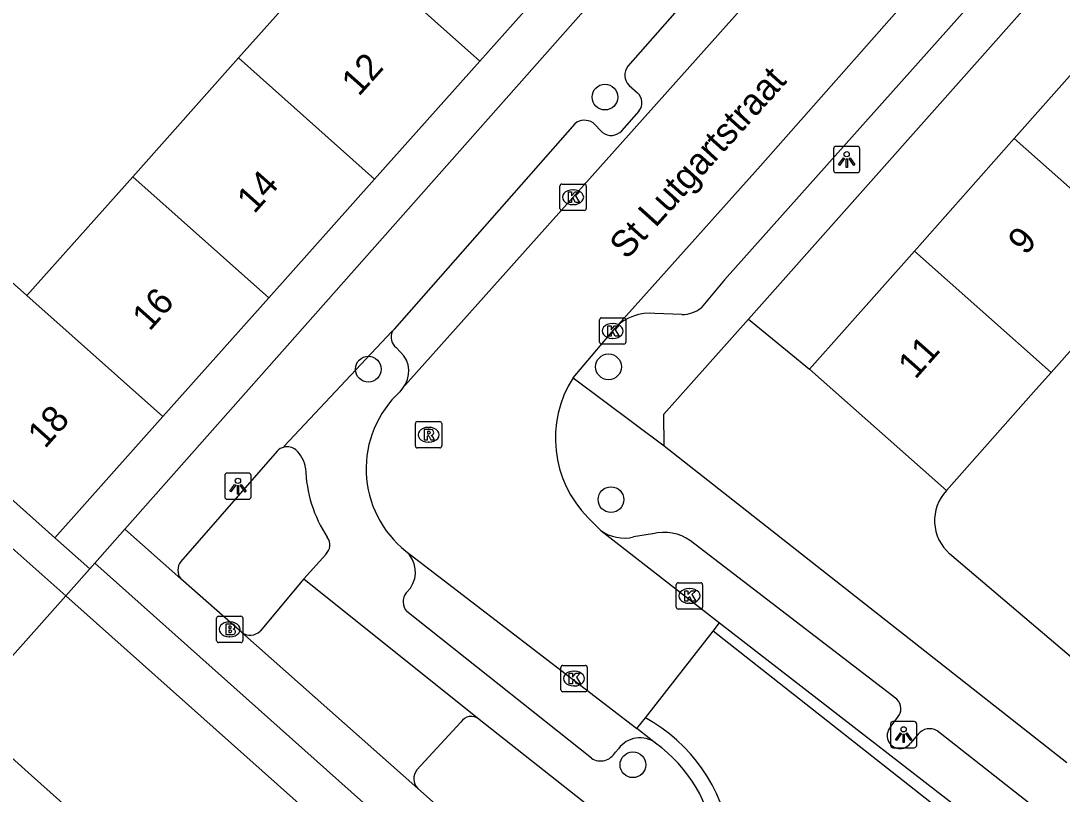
# Model space of a CAD drawing. Extents: x 162812 to 163818, y 381639 to 382470.
# Drawn here: x 162894.41 to 162934, y 382010.31 to 382039.7 of the extents above; entities that cross this region are included whole.
import ezdxf

# ---------------------------------------------------------------- set-up
doc = ezdxf.new("R2010")
doc.units = 0
for name, color, linetype in [('IMGEO_Boom', 7, 'Continuous'), ('IMGEO_Brandkraan', 7, 'Continuous'), ('IMGEO_Groenvoorziening', 7, 'Continuous'), ('IMGEO_Kolk', 7, 'Continuous'), ('IMGEO_Lichtpunt', 7, 'Continuous'), ('IMGEO_Openbare_ruimte_label', 7, 'Continuous'), ('IMGEO_Pand', 7, 'Continuous'), ('IMGEO_Pand_nummerreeks', 7, 'Continuous'), ('IMGEO_Pand_overbouw', 7, 'Continuous'), ('IMGEO_Rijbaan_lokaal_open', 7, 'Continuous'), ('IMGEO_Rioolput', 7, 'Continuous'), ('IMGEO_Voetpad_open', 7, 'Continuous')]:
    doc.layers.add(name, color=color, linetype=linetype)

msp = doc.modelspace()

# ---------------------------------------------------------------- linework, layer by layer
at = {"layer": 'IMGEO_Boom'}
for centre in [(162916.617, 382036.802), (162907.619, 382026.464), (162916.751, 382026.553), (162916.846, 382021.506), (162917.679, 382011.429)]:
    msp.add_circle(centre, 0.489, dxfattribs=at)
at = {"layer": 'IMGEO_Brandkraan'}
for p, q in [((162901.85, 382016.15), (162901.85, 382017.002)), ((162901.925, 382017.076), (162902.777, 382017.076)), ((162902.338, 382016.856), (162902.363, 382016.856)), ((162902.851, 382017.002), (162902.851, 382016.15)), ((162902.777, 382016.076), (162901.925, 382016.076)), ((162902.361, 382016.296), (162902.336, 382016.296))]:
    msp.add_line(p, q, dxfattribs=at)
for points in [[(162901.85, 382016.15), (162901.85, 382017.002)], [(162901.925, 382017.076), (162902.777, 382017.076)], [(162902.851, 382017.002), (162902.851, 382016.15)], [(162902.198, 382016.776), (162902.198, 382016.376), (162902.411, 382016.376)], [(162902.429, 382016.776), (162902.198, 382016.776)], [(162902.377, 382016.695), (162902.323, 382016.695), (162902.323, 382016.619)], [(162902.323, 382016.619), (162902.376, 382016.619)], [(162902.385, 382016.543), (162902.323, 382016.543), (162902.323, 382016.462)], [(162902.323, 382016.462), (162902.385, 382016.462)], [(162902.777, 382016.076), (162901.925, 382016.076)]]:
    msp.add_lwpolyline(points, dxfattribs=at)
for centre, radius, start, end in [((162901.927, 382017), 0.0765, 91.552, 178.448), ((162901.927, 382017), 0.0765, 91.552, 178.448), ((162902.775, 382017), 0.0765, 1.552, 88.448), ((162902.775, 382017), 0.0765, 1.552, 88.448), ((162902.378, 382016.657), 0.0379, 267.8285, 90.9355), ((162902.386, 382016.502), 0.0404, 269.8759, 90.5077), ((162902.433, 382016.631), 0.145, 59.4692, 91.5367), ((162902.458, 382016.678), 0.0922, 285.5137, 58.1501), ((162902.463, 382016.486), 0.105, 301.3115, 78.989), ((162901.927, 382016.152), 0.0765, 181.552, 268.448), ((162901.927, 382016.152), 0.0765, 181.552, 268.448), ((162902.417, 382016.627), 0.251, 268.6676, 293.5347), ((162902.775, 382016.152), 0.0765, 271.552, 358.448), ((162902.775, 382016.152), 0.0765, 271.552, 358.448)]:
    msp.add_arc(centre, radius, start, end, dxfattribs=at)
for centre, major_axis, ratio, start_param, end_param in [((162902.337, 382016.576), (-0.387, 0.002), 0.722429, 4.712389, 7.853982), ((162902.362, 382016.576), (-0.39, 0.002), 0.717154, 1.570796, 4.712389)]:
    msp.add_ellipse(centre, major_axis=major_axis, ratio=ratio, start_param=start_param, end_param=end_param, dxfattribs=at)
at = {"layer": 'IMGEO_Groenvoorziening'}
for points in [[(162922.075, 382028.37), (162924.398, 382026.461)], [(162936.109, 382014.006), (162929.716, 382019.448)]]:
    msp.add_lwpolyline(points, dxfattribs=at)
msp.add_arc((162930.828, 382020.708), 1.68, 137.2155, 228.5546, dxfattribs=at)
at = {"layer": 'IMGEO_Kolk'}
for p, q in [((162914.98, 382033.497), (162915.832, 382033.497)), ((162914.905, 382032.571), (162914.905, 382033.423)), ((162915.393, 382033.277), (162915.418, 382033.277)), ((162915.906, 382033.423), (162915.906, 382032.571)), ((162915.416, 382032.717), (162915.391, 382032.717)), ((162915.832, 382032.497), (162914.98, 382032.497)), ((162916.41, 382027.489), (162916.41, 382028.341)), ((162916.485, 382028.415), (162917.337, 382028.415)), ((162917.411, 382028.341), (162917.411, 382027.489)), ((162916.898, 382028.195), (162916.923, 382028.195)), ((162916.921, 382027.635), (162916.896, 382027.635)), ((162917.337, 382027.415), (162916.485, 382027.415)), ((162919.329, 382017.42), (162919.329, 382018.272)), ((162919.404, 382018.346), (162920.256, 382018.346)), ((162919.817, 382018.126), (162919.842, 382018.126)), ((162920.33, 382018.272), (162920.33, 382017.42)), ((162920.256, 382017.346), (162919.404, 382017.346)), ((162919.84, 382017.566), (162919.815, 382017.566)), ((162914.939, 382014.28), (162914.939, 382015.132)), ((162915.014, 382015.206), (162915.866, 382015.206)), ((162915.427, 382014.986), (162915.452, 382014.986)), ((162915.94, 382015.132), (162915.94, 382014.28)), ((162915.866, 382014.206), (162915.014, 382014.206)), ((162915.45, 382014.426), (162915.425, 382014.426))]:
    msp.add_line(p, q, dxfattribs=at)
for points in [[(162914.98, 382033.497), (162915.832, 382033.497)], [(162914.905, 382032.571), (162914.905, 382033.423)], [(162915.226, 382033.197), (162915.349, 382033.197), (162915.349, 382033.046), (162915.479, 382033.197), (162915.643, 382033.197), (162915.497, 382033.046), (162915.65, 382032.797), (162915.498, 382032.797), (162915.413, 382032.961), (162915.349, 382032.894), (162915.349, 382032.797), (162915.226, 382032.797), (162915.226, 382033.197)], [(162915.906, 382033.423), (162915.906, 382032.571)], [(162915.832, 382032.497), (162914.98, 382032.497)], [(162916.41, 382027.489), (162916.41, 382028.341)], [(162916.485, 382028.415), (162917.337, 382028.415)], [(162917.411, 382028.341), (162917.411, 382027.489)], [(162916.731, 382028.115), (162916.854, 382028.115), (162916.854, 382027.964), (162916.984, 382028.115), (162917.148, 382028.115), (162917.002, 382027.964), (162917.155, 382027.715), (162917.003, 382027.715), (162916.918, 382027.879), (162916.854, 382027.812), (162916.854, 382027.715), (162916.731, 382027.715), (162916.731, 382028.115)], [(162917.337, 382027.415), (162916.485, 382027.415)], [(162919.329, 382017.42), (162919.329, 382018.272)], [(162919.404, 382018.346), (162920.256, 382018.346)], [(162919.65, 382018.046), (162919.773, 382018.046), (162919.773, 382017.895), (162919.903, 382018.046), (162920.067, 382018.046), (162919.921, 382017.895), (162920.074, 382017.646), (162919.922, 382017.646), (162919.837, 382017.81), (162919.773, 382017.743), (162919.773, 382017.646), (162919.65, 382017.646), (162919.65, 382018.046)], [(162920.33, 382018.272), (162920.33, 382017.42)], [(162920.256, 382017.346), (162919.404, 382017.346)], [(162914.939, 382014.28), (162914.939, 382015.132)], [(162915.014, 382015.206), (162915.866, 382015.206)], [(162915.26, 382014.906), (162915.383, 382014.906), (162915.383, 382014.755), (162915.513, 382014.906), (162915.677, 382014.906), (162915.531, 382014.755), (162915.684, 382014.506), (162915.532, 382014.506), (162915.447, 382014.67), (162915.383, 382014.603), (162915.383, 382014.506), (162915.26, 382014.506), (162915.26, 382014.906)], [(162915.94, 382015.132), (162915.94, 382014.28)], [(162915.866, 382014.206), (162915.014, 382014.206)]]:
    msp.add_lwpolyline(points, dxfattribs=at)
for centre, start, end in [((162914.982, 382033.421), 91.552, 178.448), ((162914.982, 382033.421), 91.552, 178.448), ((162915.83, 382033.421), 1.552, 88.448), ((162915.83, 382033.421), 1.552, 88.448), ((162914.982, 382032.573), 181.552, 268.448), ((162914.982, 382032.573), 181.552, 268.448), ((162915.83, 382032.573), 271.552, 358.448), ((162915.83, 382032.573), 271.552, 358.448), ((162916.487, 382028.339), 91.552, 178.448), ((162916.487, 382028.339), 91.552, 178.448), ((162917.335, 382028.339), 1.552, 88.448), ((162917.335, 382028.339), 1.552, 88.448), ((162916.487, 382027.491), 181.552, 268.448), ((162916.487, 382027.491), 181.552, 268.448), ((162917.335, 382027.491), 271.552, 358.448), ((162917.335, 382027.491), 271.552, 358.448), ((162919.406, 382018.27), 91.552, 178.448), ((162919.406, 382018.27), 91.552, 178.448), ((162920.254, 382018.27), 1.552, 88.448), ((162920.254, 382018.27), 1.552, 88.448), ((162919.406, 382017.422), 181.552, 268.448), ((162919.406, 382017.422), 181.552, 268.448), ((162920.254, 382017.422), 271.552, 358.448), ((162920.254, 382017.422), 271.552, 358.448), ((162915.016, 382015.13), 91.552, 178.448), ((162915.016, 382015.13), 91.552, 178.448), ((162915.864, 382015.13), 1.552, 88.448), ((162915.864, 382015.13), 1.552, 88.448), ((162915.016, 382014.282), 181.552, 268.448), ((162915.016, 382014.282), 181.552, 268.448), ((162915.864, 382014.282), 271.552, 358.448), ((162915.864, 382014.282), 271.552, 358.448)]:
    msp.add_arc(centre, 0.0765, start, end, dxfattribs=at)
for centre, major_axis, ratio, start_param, end_param in [((162915.392, 382032.997), (-0.387, 0.002), 0.722429, 4.712389, 7.853982), ((162915.417, 382032.997), (-0.39, 0.002), 0.717154, 1.570796, 4.712389), ((162916.897, 382027.915), (-0.387, 0.002), 0.722429, 4.712389, 7.853982), ((162916.922, 382027.915), (-0.39, 0.002), 0.717154, 1.570796, 4.712389), ((162919.816, 382017.846), (-0.387, 0.002), 0.722429, 4.712389, 7.853982), ((162919.841, 382017.846), (-0.39, 0.002), 0.717154, 1.570796, 4.712389), ((162915.426, 382014.706), (-0.387, 0.002), 0.722429, 4.712389, 7.853982), ((162915.451, 382014.706), (-0.39, 0.002), 0.717154, 1.570796, 4.712389)]:
    msp.add_ellipse(centre, major_axis=major_axis, ratio=ratio, start_param=start_param, end_param=end_param, dxfattribs=at)
at = {"layer": 'IMGEO_Lichtpunt'}
for p, q in [((162925.308, 382034.835), (162925.308, 382034.028)), ((162925.308, 382034.835), (162925.308, 382034.028)), ((162926.21, 382034.93), (162925.402, 382034.93)), ((162926.21, 382034.93), (162925.402, 382034.93)), ((162926.304, 382034.028), (162926.304, 382034.835)), ((162926.304, 382034.028), (162926.304, 382034.835)), ((162925.402, 382033.934), (162926.21, 382033.934)), ((162925.402, 382033.934), (162926.21, 382033.934)), ((162902.165, 382022.422), (162902.165, 382021.615)), ((162902.165, 382022.422), (162902.165, 382021.615)), ((162903.067, 382022.517), (162902.259, 382022.517)), ((162903.067, 382022.517), (162902.259, 382022.517)), ((162903.161, 382021.615), (162903.161, 382022.422)), ((162903.161, 382021.615), (162903.161, 382022.422)), ((162902.259, 382021.521), (162903.067, 382021.521)), ((162902.259, 382021.521), (162903.067, 382021.521)), ((162927.472, 382012.98), (162927.472, 382012.173)), ((162927.472, 382012.98), (162927.472, 382012.173)), ((162928.374, 382013.075), (162927.566, 382013.075)), ((162928.374, 382013.075), (162927.566, 382013.075)), ((162928.468, 382012.173), (162928.468, 382012.98)), ((162928.468, 382012.173), (162928.468, 382012.98)), ((162927.566, 382012.079), (162928.374, 382012.079)), ((162927.566, 382012.079), (162928.374, 382012.079))]:
    msp.add_line(p, q, dxfattribs=at)
for points in [[(162925.682, 382034.499), (162925.721, 382034.471), (162925.533, 382034.209), (162925.495, 382034.236), (162925.682, 382034.499)], [(162925.784, 382034.451), (162925.831, 382034.451), (162925.831, 382034.129), (162925.784, 382034.129), (162925.784, 382034.451)], [(162925.894, 382034.471), (162925.932, 382034.498), (162926.119, 382034.236), (162926.08, 382034.208), (162925.894, 382034.471)], [(162902.539, 382022.086), (162902.578, 382022.058), (162902.39, 382021.796), (162902.352, 382021.823), (162902.539, 382022.086)], [(162902.641, 382022.038), (162902.688, 382022.038), (162902.688, 382021.716), (162902.641, 382021.716), (162902.641, 382022.038)], [(162902.751, 382022.058), (162902.789, 382022.085), (162902.976, 382021.823), (162902.937, 382021.795), (162902.751, 382022.058)], [(162927.846, 382012.644), (162927.885, 382012.616), (162927.697, 382012.354), (162927.659, 382012.381), (162927.846, 382012.644)], [(162927.948, 382012.596), (162927.995, 382012.596), (162927.995, 382012.274), (162927.948, 382012.274), (162927.948, 382012.596)], [(162928.058, 382012.616), (162928.096, 382012.643), (162928.283, 382012.381), (162928.244, 382012.353), (162928.058, 382012.616)]]:
    msp.add_lwpolyline(points, dxfattribs=at)
for centre in [(162925.807, 382034.633), (162902.664, 382022.22), (162927.971, 382012.778)]:
    msp.add_circle(centre, 0.0994, dxfattribs=at)
for centre, start, end in [((162925.402, 382034.835), 90, 180), ((162925.402, 382034.835), 90, 180), ((162926.21, 382034.835), 0, 90), ((162926.21, 382034.835), 0, 90), ((162925.402, 382034.028), 180, 270), ((162925.402, 382034.028), 180, 270), ((162926.21, 382034.028), 270, 0), ((162926.21, 382034.028), 270, 360), ((162902.259, 382022.422), 90, 180), ((162902.259, 382022.422), 90, 180), ((162903.067, 382022.422), 0, 90), ((162903.067, 382022.422), 0, 90), ((162902.259, 382021.615), 180, 270), ((162902.259, 382021.615), 180, 270), ((162903.067, 382021.615), 270, 0), ((162903.067, 382021.615), 270, 360), ((162927.566, 382012.98), 90, 180), ((162927.566, 382012.98), 90, 180), ((162928.374, 382012.98), 0, 90), ((162928.374, 382012.98), 0, 90), ((162927.566, 382012.173), 180, 270), ((162927.566, 382012.173), 180, 270), ((162928.374, 382012.173), 270, 0), ((162928.374, 382012.173), 270, 360)]:
    msp.add_arc(centre, 0.0946, start, end, dxfattribs=at)
at = {"layer": 'IMGEO_Pand'}
for points in [[(162906.69, 382042.781), (162902.686, 382038.29)], [(162906.69, 382042.781), (162911.858, 382038.173)], [(162911.858, 382038.173), (162915.664, 382042.443)], [(162932.179, 382035.23), (162935.991, 382039.525)], [(162902.686, 382038.29), (162898.664, 382033.778)], [(162907.855, 382033.683), (162902.686, 382038.29)], [(162907.855, 382033.683), (162911.858, 382038.173)], [(162928.379, 382030.947), (162932.179, 382035.23)], [(162937.377, 382030.619), (162932.179, 382035.23)], [(162898.664, 382033.778), (162894.644, 382029.268)], [(162898.664, 382033.778), (162903.833, 382029.17)], [(162903.833, 382029.17), (162907.855, 382033.683)], [(162888.693, 382026.299), (162892.789, 382030.894), (162894.644, 382029.268)], [(162924.398, 382026.461), (162928.379, 382030.947)], [(162933.576, 382026.335), (162928.379, 382030.947)], [(162933.576, 382026.335), (162937.377, 382030.619)], [(162894.644, 382029.268), (162899.812, 382024.661)], [(162899.812, 382024.661), (162903.833, 382029.17)], [(162924.398, 382026.461), (162929.595, 382021.849)], [(162929.595, 382021.849), (162932.914, 382025.589), (162933.576, 382026.335)], [(162895.703, 382020.051), (162891.971, 382023.378), (162890.534, 382024.658), (162888.693, 382026.299)], [(162899.812, 382024.661), (162895.703, 382020.051)], [(162893.84, 382019.876), (162896.127, 382017.855)], [(162896.127, 382017.855), (162892.152, 382013.4)], [(162910.955, 382006.836), (162909.879, 382005.585), (162896.127, 382017.855)], [(162892.152, 382013.4), (162894.821, 382011.019), (162907.817, 381999.423)]]:
    msp.add_lwpolyline(points, dxfattribs=at)
at = {"layer": 'IMGEO_Pand_overbouw'}
msp.add_lwpolyline([(162896.127, 382017.855), (162909.879, 382005.585), (162910.955, 382006.836), (162897.226, 382019.086)], close=True, dxfattribs=at)
at = {"layer": 'IMGEO_Rijbaan_lokaal_open'}
for points in [[(162940.419, 382061.006), (162908.926, 382025.738)], [(162917.005, 382028.023), (162922.534, 382034.193), (162929.723, 382042.344), (162932.733, 382045.731), (162937.653, 382051.145), (162938.019, 382051.566)], [(162915.402, 382026.137), (162917.005, 382028.023)], [(162908.926, 382025.738), (162908.824, 382025.608)], [(162916.457, 382020.33), (162915.978, 382020.815)], [(162916.457, 382020.33), (162920.977, 382016.827)], [(162909.048, 382019.549), (162917.831, 382012.803)], [(162920.73, 382016.511), (162920.977, 382016.827)], [(162920.977, 382016.827), (162934.305, 382006.499)], [(162918.155, 382013.213), (162920.73, 382016.511)], [(162933.979, 382006.075), (162920.73, 382016.511)], [(162917.831, 382012.803), (162918.155, 382013.213)], [(162918.543, 382012.256), (162917.831, 382012.803)]]:
    msp.add_lwpolyline(points, dxfattribs=at)
for centre, radius, start, end in [((162919.015, 382023.836), 4.284, 147.5103, 224.8439), ((162911.525, 382022.674), 3.988, 132.6367, 231.5978), ((162915.144, 382007.68), 6.3, 315.0863, 61.4454), ((162915.122, 382007.604), 5.774, 323.9457, 53.6653)]:
    msp.add_arc(centre, radius, start, end, dxfattribs=at)
at = {"layer": 'IMGEO_Rioolput'}
for p, q in [((162909.41, 382023.546), (162909.41, 382024.398)), ((162909.485, 382024.472), (162910.337, 382024.472)), ((162910.411, 382024.398), (162910.411, 382023.546)), ((162909.898, 382024.252), (162909.923, 382024.252)), ((162909.921, 382023.692), (162909.896, 382023.692)), ((162910.337, 382023.472), (162909.485, 382023.472))]:
    msp.add_line(p, q, dxfattribs=at)
for points in [[(162909.41, 382023.546), (162909.41, 382024.398)], [(162909.485, 382024.472), (162910.337, 382024.472)], [(162910.411, 382024.398), (162910.411, 382023.546)], [(162909.999, 382024.17), (162909.747, 382024.172), (162909.747, 382023.772)], [(162909.747, 382023.772), (162909.871, 382023.772), (162909.871, 382023.934), (162909.882, 382023.934)], [(162909.925, 382024.091), (162909.871, 382024.091), (162909.871, 382024.01)], [(162909.871, 382024.01), (162909.923, 382024.01)], [(162909.929, 382023.905), (162910, 382023.772), (162910.14, 382023.772), (162910.075, 382023.898)], [(162910.337, 382023.472), (162909.485, 382023.472)]]:
    msp.add_lwpolyline(points, dxfattribs=at)
for centre, radius, start, end in [((162909.487, 382024.396), 0.0765, 91.552, 178.448), ((162909.487, 382024.396), 0.0765, 91.552, 178.448), ((162910.335, 382024.396), 0.0765, 1.552, 88.448), ((162910.335, 382024.396), 0.0765, 1.552, 88.448), ((162909.881, 382023.881), 0.0533, 26.0293, 88.6989), ((162909.907, 382024.199), 0.19, 274.7715, 282.9687), ((162909.931, 382023.995), 0.0964, 77.0061, 93.1865), ((162909.945, 382024.052), 0.0378, 276.6634, 79.6772), ((162909.998, 382024.06), 0.109, 350.3612, 89.416), ((162909.996, 382024.06), 0.112, 277.5842, 350.9817), ((162909.98, 382023.845), 0.108, 29.5134, 73.7905), ((162909.487, 382023.548), 0.0765, 181.552, 268.448), ((162909.487, 382023.548), 0.0765, 181.552, 268.448), ((162910.335, 382023.548), 0.0765, 271.552, 358.448), ((162910.335, 382023.548), 0.0765, 271.552, 358.448)]:
    msp.add_arc(centre, radius, start, end, dxfattribs=at)
for centre, major_axis, ratio, start_param, end_param in [((162909.897, 382023.972), (-0.387, 0.002), 0.722429, 4.712389, 7.853982), ((162909.922, 382023.972), (-0.39, 0.002), 0.717154, 1.570796, 4.712389)]:
    msp.add_ellipse(centre, major_axis=major_axis, ratio=ratio, start_param=start_param, end_param=end_param, dxfattribs=at)
at = {"layer": 'IMGEO_Voetpad_open'}
for points in [[(162939.702, 382067.058), (162898.37, 382020.378)], [(162922.075, 382028.37), (162948.951, 382058.608)], [(162921.15, 382042.148), (162917.488, 382037.977)], [(162929.979, 382041.25), (162930.725, 382040.584), (162921.155, 382029.858), (162920.269, 382028.791)], [(162917.531, 382037.248), (162917.848, 382036.965)], [(162917.903, 382036.269), (162917.251, 382035.524)], [(162916.525, 382035.457), (162916.165, 382035.823)], [(162915.469, 382035.792), (162908.602, 382027.984)], [(162919.54, 382028.543), (162918.518, 382028.583)], [(162918.865, 382023.545), (162918.856, 382024.749), (162922.075, 382028.37)], [(162908.54, 382027.894), (162908.519, 382027.895), (162904.421, 382023.535), (162904.417, 382023.5)], [(162908.842, 382027.115), (162908.678, 382027.282)], [(162915.402, 382026.137), (162918.865, 382023.545)], [(162918.865, 382023.545), (162934.177, 382011.519)], [(162904.153, 382023.353), (162900.491, 382019.159)], [(162898.37, 382020.378), (162897.226, 382019.086)], [(162900.498, 382018.497), (162898.37, 382020.378)], [(162895.703, 382020.051), (162897.033, 382018.87)], [(162918.43, 382020.202), (162917.707, 382020.086)], [(162927.707, 382013.918), (162919.865, 382019.942)], [(162905.999, 382019.424), (162905.174, 382018.492)], [(162896.127, 382017.855), (162897.033, 382018.87)], [(162897.033, 382018.87), (162897.226, 382019.086)], [(162897.226, 382019.086), (162910.955, 382006.836)], [(162902.815, 382016.451), (162900.498, 382018.497)], [(162905.174, 382018.492), (162903.507, 382016.508)], [(162905.174, 382018.492), (162911.835, 382013.162)], [(162909.063, 382017.966), (162909.218, 382018.147)], [(162916.099, 382011.678), (162909.084, 382017.252)], [(162902.815, 382016.451), (162909.498, 382010.533)], [(162911.133, 382013.051), (162909.468, 382011.233)], [(162911.835, 382013.162), (162918.224, 382008.118)], [(162927.456, 382012.849), (162927.733, 382013.225)], [(162928.525, 382012.597), (162928.234, 382012.253)], [(162939.983, 382004.281), (162929.241, 382012.721)], [(162917.137, 382012.041), (162917.014, 382011.915)], [(162909.498, 382010.533), (162915.518, 382005.2)]]:
    msp.add_lwpolyline(points, dxfattribs=at)
for centre, radius, start, end in [((162917.932, 382037.637), 0.559, 142.5992, 224.1522), ((162917.539, 382036.59), 0.486, 318.5713, 50.4652), ((162915.838, 382035.331), 0.591, 56.4236, 128.677), ((162916.852, 382035.885), 0.539, 232.6818, 317.8636), ((162919.551, 382029.705), 1.162, 269.4431, 308.1327), ((162918.317, 382026.803), 1.791, 83.5486, 137.073), ((162908.967, 382027.669), 0.482, 152.15, 233.2642), ((162909.012, 382027.635), 0.538, 139.6088, 151.2661), ((162908.16, 382026.382), 1.001, 319.9478, 47.0339), ((162904.528, 382022.991), 0.521, 102.2518, 135.9679), ((162904.529, 382022.978), 0.534, 51.5526, 102.0814), ((162904.137, 382022.561), 1.105, 7.2549, 49.0611), ((162910.295, 382022.854), 5.064, 181.7366, 213.193), ((162905.669, 382019.785), 0.489, 312.4523, 37.473), ((162917.358, 382021.624), 1.577, 235.1435, 282.766), ((162918.877, 382018.577), 1.685, 54.0962, 105.3644), ((162908.373, 382018.756), 1.041, 324.2194, 49.608), ((162900.912, 382018.832), 0.533, 142.1878, 219.0239), ((162909.505, 382017.622), 0.56, 142.0908, 221.2786), ((162903.127, 382016.894), 0.541, 234.8327, 314.585), ((162927.382, 382013.559), 0.485, 316.4515, 47.8457), ((162911.536, 382012.779), 0.486, 52.0227, 145.9477), ((162927.834, 382012.536), 0.49, 140.3433, 324.7476), ((162917.946, 382011.457), 0.998, 53.2353, 144.1529), ((162928.956, 382012.236), 0.563, 59.6131, 140.0375), ((162916.448, 382012.216), 0.641, 237.0173, 332.0255), ((162909.858, 382010.899), 0.513, 139.4158, 225.4923)]:
    msp.add_arc(centre, radius, start, end, dxfattribs=at)

# ---------------------------------------------------------------- texts
at = {"layer": 'IMGEO_Openbare_ruimte_label'}
msp.add_text('St Lutgartstraat', height=1, rotation=48, dxfattribs=at).set_placement((162917.443, 382030.595))
at = {"layer": 'IMGEO_Pand_nummerreeks'}
for s, rotation, p in [('12', 48.2843, (162907.257, 382036.798)), ('14', 48.2843, (162903.28, 382032.337)), ('9', 48.4137, (162932.596, 382030.757)), ('16', 48.2843, (162899.301, 382027.874)), ('11', 48.4137, (162928.415, 382026.046)), ('18', 48.2832, (162895.325, 382023.412))]:
    msp.add_text(s, height=1, rotation=rotation, dxfattribs=at).set_placement(p)

doc.saveas('drawing.dxf')
